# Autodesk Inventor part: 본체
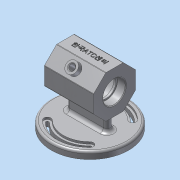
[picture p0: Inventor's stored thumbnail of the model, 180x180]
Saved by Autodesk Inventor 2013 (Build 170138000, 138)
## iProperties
Created: 2017-06
Part Number: 본체
Material: 알루미늄 6061
Document SubType Name: Modeling
Designer: Administrator
Density: 2.71 g/cm^3
Mass: 562.134 g
Surface Area: 560.522 cm^2
Volume: 207.429 cm^3
Author: Administrator
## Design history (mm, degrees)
sketch "스케치1" dims "d0" = 60
  geometry: L1 (30, -12.426)-(12.426, -30); L2 (12.426, -30)-(-12.426, -30); L3 (-12.426, -30)-(-30, -12.426); L4 (-30, -12.426)-(-30, 12.426); L5 (-30, 12.426)-(-12.426, 30); L6 (-12.426, 30)-(12.426, 30); L7 (12.426, 30)-(30, 12.426); L8 (30, 12.426)-(30, -12.426); 5 further points
  constraints: 16 end point, 3 coincident, 2 horizontal alignment, 1 midpoint, 19 other
extrude "돌출1" new body sketch "스케치1" stored distance "d1" = 70; taper "d2" = 0 deg
sketch "스케치2"
  geometry: 1 further point
hole "구멍1" sketch "스케치2" at (0, 0) diameter "d3" = 28; stored, may be unused: countersink angle "d7" = 90 deg, drill point angle "d9" = 118 deg; dims "d4" = 6, "d5" = 4, "d6" = 2, "d8" = 8
hole "구멍2" diameter "d12" = 32; stored, may be unused: countersink angle "d16" = 90 deg, drill point angle "d18" = 0 deg; dims "d10" = 10, "d11" = 10, "d13" = 6, "d14" = 4, "d15" = 2, "d17" = 12
sketch "스케치3"
  geometry: L1 (30, -12.426)-(12.426, -30) reference; L2 (12.426, -30)-(-12.426, -30) reference; L3 (-12.426, -30)-(-30, -12.426) reference; L4 (-30, -12.426)-(-30, 12.426) reference; L5 (-30, 12.426)-(-12.426, 30) reference; L6 (-12.426, 30)-(12.426, 30) reference; L7 (12.426, 30)-(30, 12.426) reference; L8 (30, 12.426)-(30, -12.426) reference; C1 r 25 at (0, 0); C2 r 14 at (0, 0) reference; 1 further point
  constraints: 1 centre point, 1 coincident
  dimensions: "d19" = 50 diameter of C1
extrude "돌출2" cut sketch "스케치3" stored distance "d20" = 40; taper "d21" = 0 deg
node "작업 평면1"
sketch "스케치4"
  geometry: C1 r 55 at (0, 0); 1 further point
  constraints: 1 centre point, 1 coincident
  dimensions: "d23" = 110 diameter of C1
extrude "돌출3" join sketch "스케치4" distance "d24" = 10; taper "d25" = 0 deg
sketch "스케치5"
  geometry: L1 (0, 0)-(33.941, 33.941); L2 (0, 0)-(48, 0); L3 (0, 0)-(-33.941, 33.941); L4 (0, 0)-(48, 0); C1 r 55 at (0, 0) reference; A1 r 43 centre (0, 0) between (30.406, 30.406) and (-30.406, 30.406); A2 r 38 centre (0, 0) between (-26.87, 26.87) and (26.87, 26.87); A3 r 48 centre (0, 0) between (-33.941, 33.941) and (33.941, 33.941); A4 r 5 centre (30.406, 30.406) between (33.73, 26.67) and (33.941, 33.941); A5 r 5 centre (-30.406, 30.406) between (-33.941, 33.941) and (-26.87, 26.87); A6 r 38 centre (0, 0) between (26.87, 26.87) and (-26.87, 26.87); A7 r 48 centre (0, 0) between (33.941, 33.941) and (-33.941, 33.941); A8 r 5 centre (-30.406, 30.406) between (-26.67, 33.73) and (-33.941, 33.941); A9 r 5 centre (-30.406, 30.406) between (-26.87, 26.87) and (-26.67, 33.73); A10 r 5 centre (30.406, 30.406) between (26.87, 26.87) and (33.73, 26.67); A11 r 5 centre (30.406, 30.406) between (33.941, 33.941) and (26.87, 26.87)
  constraints: 26 point on circle, 11 centre point, 8 end point, 3 coincident, 3 point on line, 2 equal length, 2 horizontal, 1 perpendicular
  dimensions: "d26" = 86 diameter of A1; "d27" = 76 diameter of A2; "d28" = 96 diameter of A3; "d30" = 45 deg angle of L2 L1; "d31" = 48 distance of L1.start L3.end; "d32" = 135 deg angle of L4 L3 (derived); "d33" = 10 diameter of A5
extrude "돌출4" cut sketch "스케치5" distance "d34" = 3; taper "d35" = 0 deg
sketch "스케치6"
  geometry: A1 r 38 centre (0, 0) between (26.87, 26.87) and (-26.87, 26.87) reference; A2 r 5 centre (-30.406, 30.406) between (-33.941, 33.941) and (-26.87, 26.87) reference; A3 r 48 centre (0, 0) between (33.941, 33.941) and (-33.941, 33.941) reference; A4 r 5 centre (30.406, 30.406) between (26.87, 26.87) and (33.941, 33.941) reference; A5 r 45 centre (0, 0) between (31.82, 31.82) and (-31.82, 31.82); A6 r 2 centre (-30.406, 30.406) between (-31.82, 31.82) and (-28.991, 28.991); A7 r 41 centre (0, 0) between (28.991, 28.991) and (-28.991, 28.991); A8 r 2 centre (30.406, 30.406) between (28.991, 28.991) and (31.82, 31.82)
  constraints: 8 point on circle, 4 centre point, 3 other
  dimensions: "d38" = 4 radial gap between concentric circles of A7 A5
extrude "돌출5" cut sketch "스케치6" stored distance "d40" = 3; taper "d41" = 0 deg
sketch "스케치7"
  geometry: L1 (-24, 5)-(24, 5); L2 (24, 5)-(24, -5); L3 (24, -5)-(-24, -5); L4 (-24, -5)-(-24, 5); L5 (-24, 5)-(24, -5); L6 (24, 5)-(-24, -5); C1 r 55 at (0, 0) reference; 2 further points
  constraints: 12 end point, 4 midpoint, 2 parallel, 2 vertical alignment, 1 horizontal, 1 perpendicular, 4 other
  dimensions: "d42" = 48 distance of L1.start L1.end; "d44" = 10 distance of L1.end L2.end
extrude "돌출6" join sketch "스케치7" stored distance "d45" = 3; taper "d46" = 0 deg
fillet "모깎기1" dims "d47" = 5
fillet "모깎기2" dims "d48" = 3
fillet "모깎기3" dims "d49" = 0.3
fillet "모깎기4" dims "d50" = 3
sketch "스케치10"
  geometry: L1 (0, 0)-(-37.278, 37.278); L2 (0, 0)-(52.72, 0); L3 (-20.506, 31.82)-(-15.556, 26.87); L4 (-23.335, 28.991)-(-18.385, 24.042); L5 (30, 12.426)-(30, -12.426) reference; L6 (30, -12.426)-(12.426, -30) reference; L7 (12.426, -30)-(-12.426, -30) reference; L8 (-12.426, -30)-(-30, -12.426) reference; L9 (-30, -12.426)-(-30, 12.426) reference; L10 (-30, 12.426)-(-12.426, 30) reference; L11 (-12.426, 30)-(12.426, 30) reference; L12 (12.426, 30)-(30, 12.426) reference; L13 (-30, 12.426)-(-12.426, 30) reference; L14 (-23.335, 28.991)-(-20.506, 31.82); L15 (-15.556, 26.87)-(3.314, 8); L16 (-18.385, 24.042)-(1.687, 3.97); C1 r 16 at (0, 0) reference
  constraints: 14 end point, 2 point on line, 1 equal length, 1 horizontal, 1 parallel
  dimensions: "d51" = 135 deg angle of L2 L1; "d52" = 16 diameter of L3 L1; "d54" = 8 diameter of L4 L1; "d55" = 7 distance between parallel lines of L13 L14
revolve "회전1" sketch "스케치10" stored, may be unused: angle "d56" = 90 deg
sketch "스케치11"
  geometry: C1 r 4 at (0, 0) reference
extrude "돌출7" cut sketch "스케치11" stored distance "d57" = 10; taper "d58" = 0 deg
chamfer "모따기1" distance "d59" = 1; stored, may be unused: second distance "d60" = 2, angle "d61" = 45 deg
fillet "모깎기5" dims "d62" = 1
node "작업 평면2"
sketch "스케치13"
  geometry: L1 (0, -24.024)-(0, 0) reference; L2 (70, 17.988)-(0, 17.988) reference; 2 further points
  constraints: 1 coincident, 1 other
  dimensions: "d64" = 35 distance from line of L1 point (35, -12.012) (derived); "d65" = 30 distance from line of point (35, -12.012) L2 (derived)
feature "엠보싱1" sketch "스케치13" dims "d66" = 0.5, "d67" = 0
node "솔리드1"
mirror "대칭1"
mirror "대칭2"
node "투영된 루프1"
node "절단 모서리 투영1"
other parameters: "d22" = -62, "d63" = 1
